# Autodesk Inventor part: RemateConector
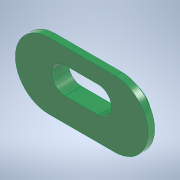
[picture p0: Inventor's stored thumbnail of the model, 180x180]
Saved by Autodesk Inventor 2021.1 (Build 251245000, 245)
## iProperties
Created: 2021-06
Part Number: RemateConector
Material: Genérico
Document SubType Name: Modeling
Designer: Ricardo
Density: 1 g/cm^3
Appearance: Suave - Naranja claro
Author: Ricardo
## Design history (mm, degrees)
sketch "Boceto1"
  geometry: L1 (-5, 0)-(5, 0); L2 (-5, -3)-(5, -3); L3 (5, 3)-(-5, 3); L4 (-5, 5)-(5, 5); L5 (5, -5)-(-5, -5); L6 (-2.5, 0.6)-(2.5, 0.6); L7 (-2.5, -1.4)-(2.5, -1.4); L8 (2.5, 2.6)-(-2.5, 2.6); A1 r 3 centre (-5, 0) between (-5, 3) and (-5, -3); A2 r 3 centre (5, 0) between (5, -3) and (5, 3); A3 r 5 centre (5, 0) between (5, -5) and (5, 5); A4 r 5 centre (-5, 0) between (-5, 5) and (-5, -5); A5 r 2 centre (-2.5, 0.6) between (-2.5, 2.6) and (-2.5, -1.4); A6 r 2 centre (2.5, 0.6) between (2.5, -1.4) and (2.5, 2.6); 4 further points
  constraints: 20 end point, 12 point on circle, 8 tangent, 6 centre point, 3 parallel, 2 horizontal, 2 midpoint, 3 other
  dimensions: "d0" = 5 distance of point (0, 0) L1.end; "d1" = 6 diameter of A2; "d2" = 2 distance between parallel lines of L3 L4; "d3" = 2.5 distance of point (0, 0.6) L6.end; "d4" = 4 diameter of A6; "d5" = 0.6 distance between parallel lines of L1 L6
extrude "Extrusión1" new body sketch "Boceto1" distance "d6" = 1; taper "d7" = 0 deg
extrude "Extrusión2" join sketch "Boceto1" distance "d8" = 1.5; taper "d9" = 0 deg
node "Sólido1"
